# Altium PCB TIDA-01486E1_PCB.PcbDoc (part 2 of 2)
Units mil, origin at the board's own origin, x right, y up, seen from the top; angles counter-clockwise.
Board outline 4100 x 3000 mil, 4 copper layers (Top Layer, Signal Layer 1, Signal Layer 2, Bottom Layer), stack 61.6 mil thick; 140 components, 71 nets, 368 pads, 137 vias.
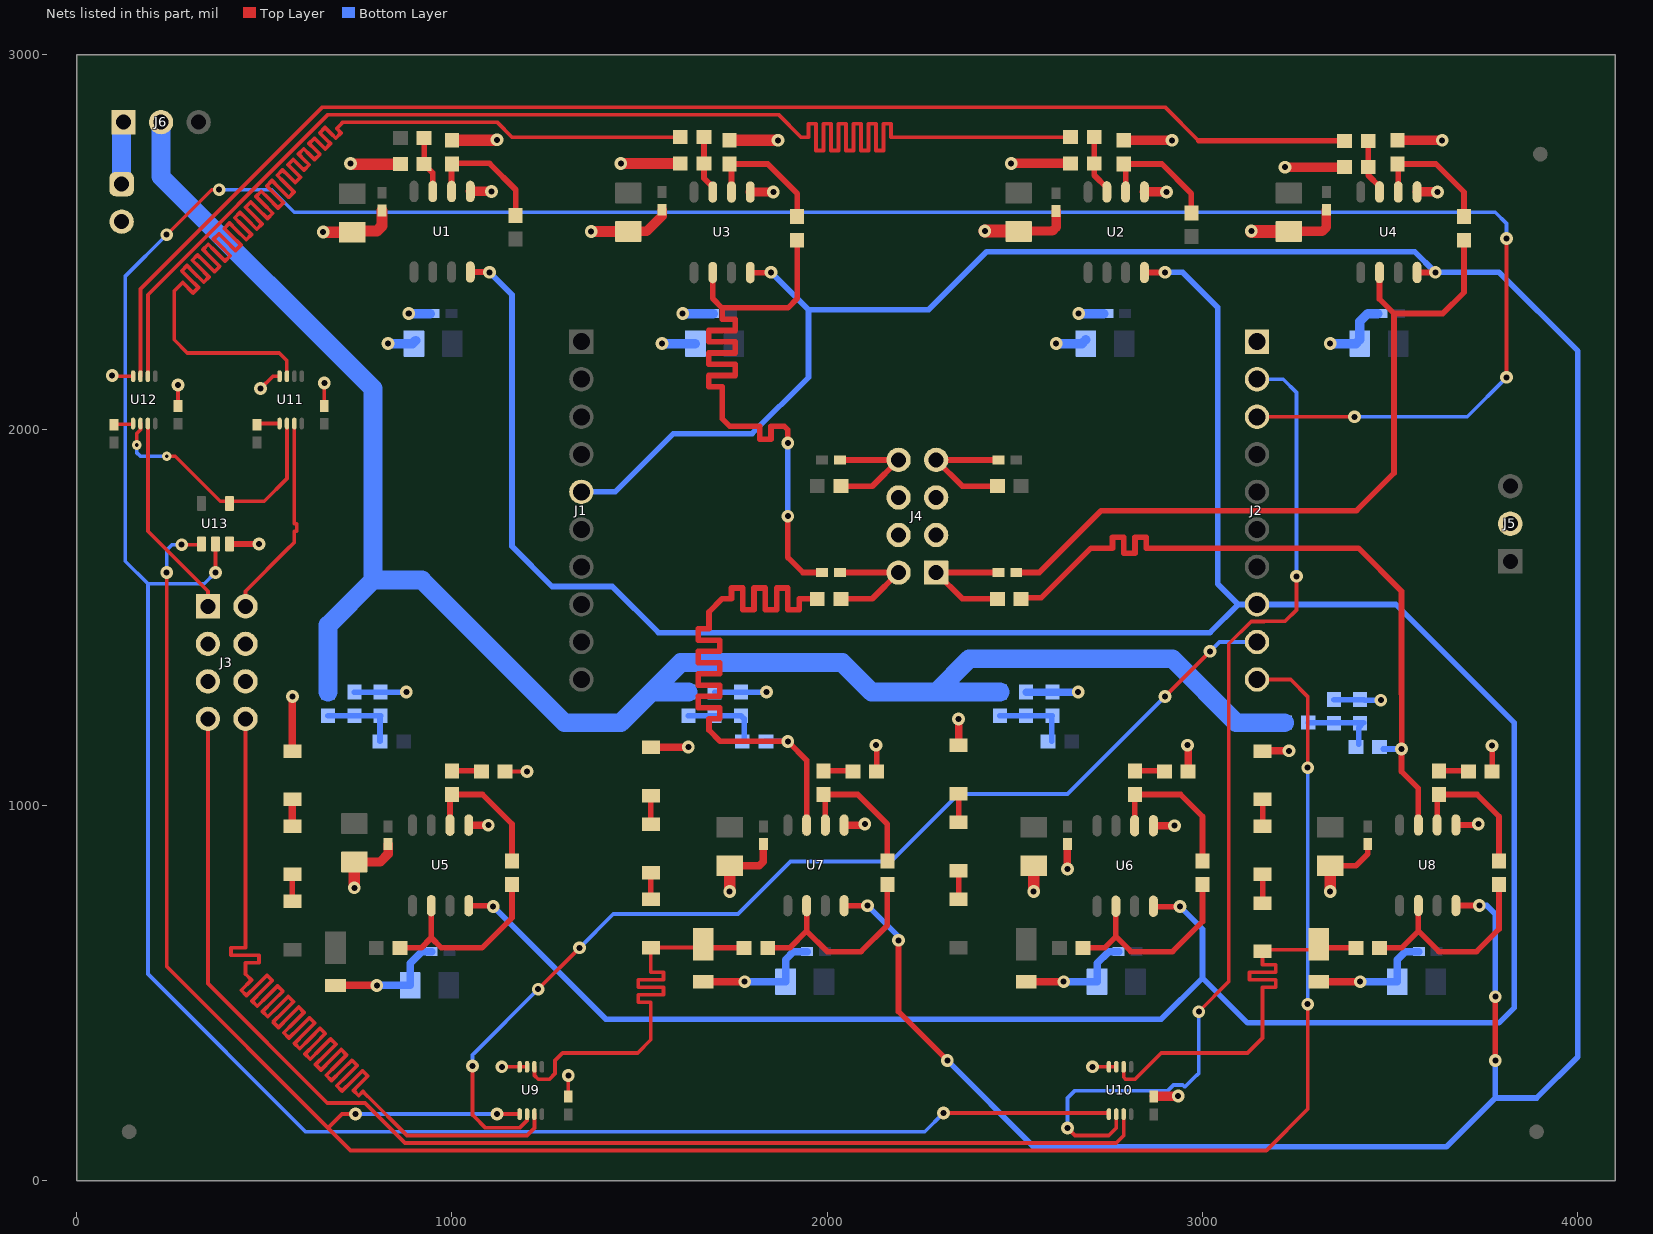
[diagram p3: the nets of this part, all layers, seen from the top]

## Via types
v1: diameter 34, hole 16, Top Layer to Bottom Layer, 129 vias
v2: diameter 40, hole 20, Top Layer to Bottom Layer, 6 vias
v3: diameter 26, hole 10, Top Layer to Bottom Layer, 2 vias

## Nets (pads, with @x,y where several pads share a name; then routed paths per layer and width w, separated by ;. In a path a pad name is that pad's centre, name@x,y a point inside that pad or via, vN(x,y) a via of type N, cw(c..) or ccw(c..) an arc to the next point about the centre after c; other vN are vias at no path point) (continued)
CH1_T: C2.2 U12.2 | length 3678.2
  Top Layer w10: U12.2@190.16,2143.31 190.16,2360.16 670,2840 1870,2840 1930,2780 1940,2780 1950,2780 1950,2815.43 1970,2815.43 1970,2780 1970,2744.57 1990,2744.57 1990,2780 1990,2815.43 2010,2815.43 2010,2780 2010,2744.57 2030,2744.57 2030,2780 2030,2815.43 2050,2815.43 2050,2780 2050,2744.57 2070,2744.57 2070,2780 2070,2815.43 2090,2815.43 2090,2780 2090,2744.57 2110,2744.57 2110,2780 2110,2815.43 2130,2815.43 2130,2780 2130,2744.57 2150,2744.57 2150,2780 2150,2815.43 2170,2815.43 2170,2780 2340,2780 C2.2@2648.5,2780
CH2_IN: C25.1 R31.2 U7.3 | length 1955.1
  Top Layer w15: U7.3@1945,946.97 1945,1120 v1(1895,1170) 1715,1170 1685,1200 1685,1230 1713.96,1230 1713.96,1260 1685,1260 1656.04,1260 1656.04,1290 1685,1290 1713.96,1290 1713.96,1320 1685,1320 1656.04,1320 1656.04,1350 1685,1350 1713.96,1350 1713.96,1380 1685,1380 1656.04,1380 1656.04,1410 1685,1410 1713.96,1410 1713.96,1440 1685,1440 1656.04,1440 1656.04,1470 1685,1470 1685,1500 1685,1515 1720,1550 1745,1550 1745,1578.96 1775,1578.96 1775,1550 1775,1521.04 1805,1521.04 1805,1550 1805,1578.96 1835,1578.96 1835,1550 1835,1521.04 1865,1521.04 1865,1550 1865,1578.96 1895,1578.96 1895,1550 1895,1521.04 1925,1521.04 1925,1550 1940,1550 C25.1@1973.5,1550
  Bottom Layer w15: R31.2@1834.45,1170 1841.5,1170 v1@1894.45,1170
CH2_OUT: R7.2 R37.2 U3.6 | length 1894.9
  Top Layer w15: U3.6@1695,2419.2 1695,2350 1720,2325 ; v1(1895,1770) 1895,1660 1935,1620 R37.2@1986.38,1620 ; v1(1895,1965) 1895,2000 1885,2010 1860,2010 1850,2010 1850,1974.67 1820,1974.67 1820,2010 1790,2010 1775,2010 1740,2010 1720,2030 1720,2115 1684.67,2115 1684.67,2145 1720,2145 1755.33,2145 1755.33,2175 1720,2175 1684.67,2175 1684.67,2205 1720,2205 1755.33,2205 1755.33,2235 1720,2235 1684.67,2235 1684.67,2265 1720,2265 1755.33,2265 1755.33,2295 1720,2295 1720,2310 1720,2325 ; R7.2@1920,2505 1920,2350 1895,2325 1720,2325
  Bottom Layer w15: v1(1895,1770) v1(1895,1965)
CH2_R: D3.1 D11.2 R41.2 U9.2 | length 1162.8
  Top Layer w10: U9.2@1219.84,302.99 1219.84,280.16 1230,270 1260,270 1275,285 1275,320 1295,340 1495,340 1530,375 1530,425 1530,475 1496.25,475 1496.25,495 1530,495 1563.75,495 1563.75,515 1530,515 1496.25,515 1496.25,535 1530,535 1563.75,535 1563.75,555 1530,555 1530,565 1530,621.26 D3.1@1666.26,621.26
  Top Layer w15: D3.1@1680.2,620 R41.2@1778.5,620
  Top Layer w20: D3.1@1672.6,627.6 D3.1@1680.2,620
CH2_T: C3.2 U11.3 | length 3678.5
  Top Layer w10: U11.3@560,2143 560,2185 540,2205 295,2205 260,2240 260,2370 282.81,2392.81 310.55,2365.06 324.69,2379.2 296.95,2406.95 280.13,2423.77 294.27,2437.92 311.09,2421.09 338.84,2393.35 352.98,2407.49 325.23,2435.23 308.41,2452.06 322.55,2466.2 339.38,2449.38 367.12,2421.63 381.26,2435.77 353.52,2463.52 336.69,2480.34 350.84,2494.48 367.66,2477.66 395.41,2449.91 409.55,2464.06 381.8,2491.8 364.98,2508.63 379.12,2522.77 395.94,2505.94 423.69,2478.2 437.83,2492.34 410.09,2520.09 393.26,2536.91 407.4,2551.05 424.23,2534.23 451.97,2506.48 466.12,2520.62 438.37,2548.37 421.55,2565.19 435.69,2579.34 452.51,2562.51 480.26,2534.77 494.4,2548.91 466.65,2576.65 449.83,2593.48 463.97,2607.62 480.8,2590.8 508.54,2563.05 522.68,2577.19 494.94,2604.94 478.12,2621.76 492.26,2635.9 509.08,2619.08 536.83,2591.34 550.97,2605.48 523.22,2633.22 506.4,2650.05 520.54,2664.19 537.37,2647.37 565.11,2619.62 579.25,2633.76 551.51,2661.51 534.68,2678.33 548.83,2692.47 565.65,2675.65 582.45,2658.85 596.59,2672.99 579.79,2689.79 562.97,2706.62 577.11,2720.76 593.93,2703.93 605.76,2692.11 619.9,2706.25 608.08,2718.08 591.25,2734.9 605.39,2749.04 622.22,2732.22 634.04,2720.39 648.18,2734.54 636.36,2746.36 619.54,2763.18 633.68,2777.33 650.5,2760.5 662.33,2748.68 676.47,2762.82 664.64,2774.64 647.82,2791.47 661.96,2805.61 678.79,2788.79 690.61,2776.96 704.75,2791.11 692.93,2802.93 700,2810 710,2820 1120,2820 1160,2780 C3.2@1608.5,2780
CH3_IN: C23.2 R32.2 U8.3 | length 1955.1
  Top Layer w15: C23.2@2516.5,1550 2516.5,1552.37 2570,1552.37 2702.63,1685 2745,1685 2760,1685 2760,1714.5 2790,1714.5 2790,1685 2790,1670.96 2820,1670.96 2820,1685 2820,1714.5 2850,1714.5 2850,1685 2995,1685 3415,1685 3530,1570 3530,1296.66 3530.88,1295.78 3530.88,1150.88 v1(3530,1150) 3530,1090 3575,1045 U8.3@3575,947.28
  Bottom Layer w15: R32.2@3481.5,1150 v1(3530,1150)
CH3_OUT: R8.2 R35.1 U4.6 | length 2015.3
  Top Layer w15: R35.1@2503.62,1620 2565,1620 2730,1785 3410,1785 3510,1885 3510,2310 ; U4.6@3471.5,2419.52 3471.5,2348.5 3510,2310 ; R8.2@3696.5,2505.31 3696.5,2366.5 3640,2310 3510,2310
CH3_R: D4.1 D14.2 R42.2 U10.2 | length 1140.6
  Top Layer w10: U10.2@2789.84,302.99 2789.84,275.16 2795,270 2820,270 2890,340 3120,340 3160,380 3160,405 3160,515 3194.89,515 3194.89,535 3160,535 3125.11,535 3125.11,555 3160,555 3194.89,555 3194.89,575 3160,575 3160,585 3160,615 D4.1@3315.2,615
  Top Layer w15: D4.1@3315.2,615 3320.2,620 R42.2@3408.5,620
CH3_T: C4.2 U12.3 | length 3678.2
  Top Layer w10: U12.3@170.47,2143.31 170.47,2375.47 655,2860 2900,2860 2990,2770
  Top Layer w15: 2990,2770 C4.2@3378.5,2770
EVM_CH0_IN: J3.8 U9.7 | length 3386.3
  Top Layer w10: J3.8@450,1230 450,1020 450,620 411.68,620 411.68,600 450,600 486.07,600 486.07,580 450,580 450,560 450,550 451.8,548.2 465.94,534.06 438.85,506.96 452.99,492.82 480.09,519.91 507.18,547.01 521.32,532.87 494.23,505.77 467.13,478.68 481.28,464.54 508.37,491.63 535.46,518.72 549.61,504.58 522.51,477.49 495.42,450.39 509.56,436.25 536.65,463.35 563.75,490.44 577.89,476.3 550.8,449.2 523.7,422.11 537.84,407.97 564.94,435.06 592.03,462.16 606.18,448.01 579.08,420.92 551.99,393.82 566.13,379.68 593.22,406.78 620.32,433.87 634.46,419.73 607.37,392.63 580.27,365.54 594.41,351.4 621.51,378.49 648.6,405.59 662.74,391.44 635.65,364.35 608.56,337.26 622.7,323.11 649.79,350.21 676.89,377.3 691.03,363.16 663.93,336.07 636.84,308.97 650.98,294.83 678.08,321.92 705.17,349.02 719.31,334.88 692.22,307.78 665.12,280.69 679.27,266.55 706.36,293.64 733.45,320.73 747.6,306.59 720.5,279.5 693.41,252.4 707.55,238.26 734.64,265.36 761.74,292.45 775.88,278.31 748.79,251.21 737.66,240.09 751.8,225.94 762.93,237.07 770,230 775.24,224.76 775.52,224.76 880.28,120 1200,120 1219.84,139.84 U9.7@1219.84,177.01
EVM_CH0_OUT: J3.2 U11.7 | length 553.2
  Top Layer w10: J3.2@450,1530 450,1570 565,1685 572.07,1692.07 580.16,1700.16 580.16,1710.16 580.16,1730.16 586.31,1730.16 586.31,1750.16 580.16,1750.16 580.16,1815 U11.7@580.16,2017.01
EVM_CH1_IN: J3.7 U10.7 | length 3386.3
  Top Layer w10: J3.7@350,1230 350,525 668.12,206.88 768.12,206.88 875,100 2770,100 2789.84,119.84 U10.7@2789.84,177.01
EVM_CH1_OUT: J3.1 U12.7 | length 553.2
  Top Layer w10: U12.7@190.16,2017.01 190.16,1729.84 350,1570 J3.1@350,1530
EXT_VBIAS: J6.1 J7.1 | length 167.1
  Bottom Layer w50: J7.1@120,2655 120,2815 J6.1@125,2820
GND: C9.2 C10.2 C11.2 C12.2 C13.2 C14.2 C15.2 C16.2 C17.2 C18.2 C19.2 C20.2 C27.1 C28.1 C29.1 C30.1 C31.2 C32.2 C33.2 C34.2 C35.2 C36.2 C37.2 C38.2 C39.2 C40.1 C41.2 C42.1 C43.2 C44.1 C45.2 C46.1 C47.2 C48.2 C49.2 C50.2 C51.2 C52.2 C53.2 C54.2 C55.2 C56.2 C57.2 C58.2 D1.2 D2.2 D3.2 D4.2 D7.1 D10.1 D13.1 D16.1 J2.1 J3.3 J3.4 J3.5 J3.6 J4.3 J4.4 J4.5 J4.6 J5.2 J7.2 R1.1 R2.1 R3.1 R4.1 R9.1 R10.1 R11.1 R12.1 R25.1 R26.1 R27.1 R28.1 U1.1 U2.1 U3.1 U4.1 U5.1 U6.1 U7.1 U8.1 U9.3 U9.4 U10.3 U10.4 U11.4 U12.4 U13.3 | length 6917.7
  Top Layer w10: v1@85,2142.99 U12.4@150.47,2142.99 ; C56.2@270,2063.62 v1(270,2120) ; v1(490,2110) 522.99,2142.99 U11.4@540.79,2142.99 ; C55.2@660,2063.62 v1(660,2125) ; v1(1132.99,302.99) U9.4@1180.47,302.99 U9.3@1200.16,302.99 ; C47.2@1141.5,1090 v1(1200,1090) ; C57.2@1310,223.62 v1(1310,280) ; v1(2707.01,302.99) U10.4@2750.47,302.99 U10.3@2770.16,302.99
  Top Layer w15: U13.3@407.4,1695.87 v1(485.87,1695.87) ; v1(2130,1160) 2131.5,1158.5 C49.2@2131.5,1090 ; C58.2@2870,223.62 C58.2@2871.38,225 ; C46.1@3340,838.82 3408.82,838.82 3440,870 C45.2@3440,896.38 ; U8.1@3675,947.28 v1@3737.28,947.28 ; C50.2@3771.5,1090 v1(3771.5,1158.5)
  Top Layer w20: D7.1@575,1150 v1(575,1290) ; D1.2@690,519.8 v1(800,519.8) ; U5.1@1045,946.97 v1(1096.97,946.97) ; D13.1@1530,1154.47 1629.47,1154.47 v1(1630,1155) ; D3.2@1670,529.8 v1@1779.8,529.8 ; C44.1@1740,838.82 1818.82,838.82 1830,850 C43.2@1830,896.38 ; U7.1@2045,946.97 v1@2096.97,946.97 ; D10.1@2350,1158.74 v1(2350,1230) ; D2.2@2530,529.8 v1@2629.8,529.8 ; v1(2640,830) C41.2@2640,896.38 ; U6.1@2869.04,945.43 v1(2925.43,945.43) ; C48.2@2961.5,1090 v1@2961.5,1158.5 ; D16.1@3170.53,1145 v1@3225,1145 ; D4.2@3310,529.8 3310.2,530 v1(3420,530)
  Top Layer w25: C40.1@740,848.82 808.82,848.82 830,870 C39.2@830,896.38 ; U1.1@1049.04,2635.43 v1(1105.43,2635.43) ; C29.1@1470,2528.82 1518.82,2528.82 1560,2570 C14.2@1560,2586.38 ; U3.1@1795,2633.77 v1(1856.23,2633.77) ; v1(2490,2710) R2.1@2648.5,2710 ; C28.1@2508.82,2530 2600,2530 2610,2540 C12.2@2610,2583.18 ; R10.1@2800,2771.5 v1(2918.5,2771.5) ; U2.1@2845,2634.09 v1(2904.09,2634.09) ; C58.2@2871.38,225 v1(2935,225) ; v1(3220,2700) R4.1@3378.5,2700 ; C30.1@3230,2528.82 3318.82,2528.82 3330,2540 C16.2@3330,2586.38 ; R12.1@3520,2771.5 v1(3638.5,2771.5) ; U4.1@3571.5,2634.09 v1(3625.91,2634.09)
  Top Layer w30: v1(656.97,2526.97) C27.1@734.36,2526.97 737.39,2530 800,2530 814.04,2544.04 C10.2@814.04,2584.84 ; v1(730,2710) 731.85,2708.15 R1.1@862.86,2708.15 ; v1(740,780) C40.1@740,848.82 ; R9.1@1000,2771.5 1118.5,2771.5 v1(1120,2772.99) ; v1(1371.18,2528.82) C29.1@1470,2528.82 ; v1(1450,2710) R3.1@1608.5,2710 ; v1(1740,770) C44.1@1740,838.82 ; R11.1@1740,2771.5 v1(1868.5,2771.5) ; v1(2550,770) C42.1@2550,838.82 ; v1(3340,770) C46.1@3340,838.82
  Top Layer w35: v1(2420,2530) C28.1@2508.82,2530 ; v1@3131.18,2528.82 C30.1@3230,2528.82
  Bottom Layer w15: R25.1@740,1301.5 C51.2@810,1301.5 v1(878.5,1301.5) ; R27.1@1700,1301.5 v1(1838.5,1301.5) ; R28.1@3350.07,1281.5 3430.26,1281.5 3431.75,1280 v1(3475,1280)
  Bottom Layer w20: v1(800,519.8) 888.62,519.8 C35.2@888.82,520 888.82,578.82 920,610 C17.2@946.38,610 ; v1(1780,530) C37.2@1888.82,530 1888.82,588.82 1910,610 C19.2@1946.38,610 ; R26.1@2530,1301.5 v1(2668.5,1301.5) ; v1(2630,530) C36.2@2718.82,530 2718.82,578.82 2750,610 C18.2@2776.38,610 ; v1(3420,530) C38.2@3518.82,530 3518.82,588.82 3540,610 C20.2@3576.38,610
  Bottom Layer w25: v1(830,2230) 895.03,2230 C31.2@903.18,2238.15 ; v1(885,2310) C9.2@942.59,2310 ; v1(1560,2230) C33.2@1648.82,2230 ; v1(1615,2310) C13.2@1696.38,2310 ; v1(2610,2230) 2678.82,2230 C32.2@2688.82,2240 ; v1(2670,2310) C11.2@2736.38,2310 ; v1(3340,2230) 3408.82,2230 3418.82,2240 3418.82,2288.82 3440,2310 C15.2@3466.38,2310
  other v1: 2100,950 3734.57,950 3230,1145 2960,1160 95,2145 3130,2530
NetC1_1: C1.1 R1.2 U1.3 | length 152.3
  Top Layer w15: C1.1@925.85,2778.15 R1.2@925.85,2708.15 949.04,2684.96 U1.3@949.04,2635.43
NetC2_1: C2.1 R2.2 U2.3 | length 159.8
  Top Layer w15: C2.1@2711.5,2780 R2.2@2711.5,2710 2711.5,2678.5 2745,2645 U2.3@2745,2634.09
NetC3_1: C3.1 R3.2 U3.3 | length 156
  Top Layer w15: C3.1@1671.5,2780 R3.2@1671.5,2710 1671.5,2670.66 1695,2647.16 U3.3@1695,2633.77
NetC4_1: C4.1 R4.2 U4.3 | length 148.3
  Top Layer w15: C4.1@3441.5,2770 R4.2@3441.5,2700 3441.5,2678.5 3471.5,2648.5 U4.3@3471.5,2634.09
NetC23_1: C23.1 J4.1 R35.2 | length 360.4
  Top Layer w15: C23.1@2455,1550 C23.1@2453.5,1550 2360,1550 J4.1@2290,1620 R35.2@2456.38,1620
NetC24_1: C24.1 J4.7 R36.2 | length 360.4
  Top Layer w15: C24.1@2455,1850 C24.1@2453.5,1850 2360,1850 J4.7@2290,1920 R36.2@2456.38,1920
NetC25_2: C25.2 J4.2 R37.1 | length 334
  Top Layer w15: R37.1@2035,1620 J4.2@2190,1620 2120,1550 C25.2@2040,1550
NetC26_2: C26.2 J4.8 R38.1 | length 334
  Top Layer w15: R38.1@2035,1920 J4.8@2190,1920 2120,1850 C26.2@2040,1850
NetC47_1: C47.1 R17.1 | length 79.1
  Top Layer w15: R17.1@1000,1091.5 1077.01,1091.5 C47.1@1078.5,1090
NetC48_1: C48.1 R18.1 | length 79.1
  Top Layer w15: R18.1@2820,1091.5 2897.01,1091.5 C48.1@2898.5,1090
NetC49_1: C49.1 R19.1 | length 77
  Top Layer w15: R19.1@1990,1091.5 C49.1@2067.01,1091.5
NetC50_1: C50.1 R20.1 | length 79.1
  Top Layer w15: R20.1@3630,1091.5 3707.01,1091.5 C50.1@3708.5,1090
NetC51_1: C51.1 R21.2 R25.2 R29.1 | length 207
  Bottom Layer w15: R21.2@670,1238.5 760,1238.5 C51.1@810,1238.5 ; R29.1@808.5,1170 C51.1@808.5,1237.01
NetC52_1: C52.1 R22.2 R26.2 R30.1 | length 207
  Bottom Layer w15: R22.2@2460,1238.5 R26.2@2530,1238.5 C52.1@2600,1238.5 ; R30.1@2598.5,1170 C52.1@2598.5,1237.01
NetC53_1: C53.1 R23.2 R27.2 R31.1 | length 212
  Bottom Layer w15: R23.2@1630,1238.5 C53.1@1770,1238.5 1778.5,1230 R31.1@1778.5,1170
NetC54_1: C54.1 R24.2 R28.2 R32.1 | length 210
  Bottom Layer w15: R24.2@3281.5,1220 3428.76,1220 3416,1207.24 R32.1@3416,1162.5
NetD5_1: D5.1 D6.2 | length 75
  Top Layer w15: D5.1@575,740 D6.2@575,815
NetD6_1: D6.1 D7.2 | length 70.5
  Top Layer w20: D6.1@575,944.47 D7.2@575,1015
NetD8_1: D8.1 D9.2 | length 70.5
  Top Layer w15: D8.1@2350,749.47 D9.2@2350,820
NetD9_1: D9.1 D10.2 | length 77.6
  Top Layer w15: D10.2@2345,1030 2350,1025 D9.1@2350,954.47
NetD11_1: D11.1 D12.2 | length 60.5
  Top Layer w15: D11.1@1530,749.47 D12.2@1530,810
NetD12_1: D12.1 D13.2 | length 75.5
  Top Layer w15: D12.1@1530,949.47 D13.2@1530,1025
NetD14_1: D14.1 D15.2 | length 60
  Top Layer w15: D14.1@3160,745 D15.2@3160,805
NetD15_1: D15.1 D16.2 | length 77.6
  Top Layer w15: D16.2@3155,1010 3160,1005 D15.1@3160,934.47
NetR5_1: R5.1 R9.2 U1.2 | length 330.8
  Top Layer w15: U1.2@999.04,2635.43 R9.2@999.04,2709.04 ; R9.2@1006.25,2714.76 1011.01,2710 1100,2710 1170,2640 1170,2585.92 R5.1@1164.04,2579.96
NetR6_1: R6.1 R10.2 U2.2 | length 323.6
  Top Layer w15: U2.2@2795,2634.09 R10.2@2795,2703.5 ; R10.2@2800,2708.5 2891.5,2708.5 2970,2630 R6.1@2970,2578.3
NetR7_1: R7.1 R11.2 U3.2 | length 351
  Top Layer w15: U3.2@1745,2633.77 1745,2703.5 R11.2@1740,2708.5 1841.5,2708.5 1920,2630 R7.1@1920,2568.3
NetR8_1: R8.1 R12.2 U4.2 | length 347.8
  Top Layer w15: U4.2@3521.5,2634.09 3521.5,2707.01 R12.2@3520,2708.5 3621.5,2708.5 3696.5,2633.5 R8.1@3696.5,2568.3
NetR13_1: R13.1 R17.2 U5.2 | length 374.6
  Top Layer w15: U5.2@995,946.97 995,1023.5 R17.2@1000,1028.5 1081.5,1028.5 1160,950 R13.1@1160,851.5
NetR13_2: R13.2 R39.1 U5.6 | length 527.9
  Top Layer w15: R39.1@861.5,620 918.19,620 945,646.81 ; U5.6@945,732.4 945,646.81 ; R13.2@1160,788.5 1160,700 1080,620 971.81,620 945,646.81
NetR14_1: R14.1 R18.2 U6.2 | length 406.2
  Top Layer w15: U6.2@2819.04,945.43 2819.04,1027.55 R18.2@2820,1028.5 2941.5,1028.5 3000,970 R14.1@3000,851.5
NetR14_2: R14.2 R40.1 U6.6 | length 560
  Top Layer w15: R40.1@2681.5,620 2739.13,620 2769.04,649.91 ; U6.6@2769.04,730.87 2769.04,649.91 ; R14.2@3000,788.5 3000,690 2920,610 2808.95,610 2769.04,649.91
NetR15_1: R15.1 R19.2 U7.2 | length 384.6
  Top Layer w15: R19.2@1990,1028.5 2081.41,1028.5 2160,949.91 R15.1@2160,851.5 ; U7.2@1995,946.97 R19.2@1995,1023.5
  Top Layer w20: R19.2@1990,1028.5 R19.2@1995,1023.5
NetR15_2: R15.2 R41.1 U7.6 | length 564.8
  Top Layer w15: R41.1@1841.5,620 1900,620 1945,665 ; U7.6@1945,732.4 1945,665 ; R15.2@2160,788.5 2160,680 2090,610 2000,610 1945,665
NetR16_1: R16.1 R20.2 U8.2 | length 386
  Top Layer w15: U8.2@3625,947.28 3625,1023.5 R20.2@3630,1028.5 3731.5,1028.5 3790,970 R16.1@3790,851.5
NetR16_2: R16.2 R42.1 U8.6 | length 571
  Top Layer w15: R42.1@3471.5,620 3530,620 3575,665 ; U8.6@3575,732.72 3575,665 ; R16.2@3790,788.5 3790,670 3730,610 3630,610 3575,665
NetR43_2: R43.2 U11.5 | length 57.1
  Top Layer w10: R43.2@483.71,2017.01 U11.5@540.79,2017.01
NetR44_2: R44.2 U12.5 | length 50.5
  Top Layer w10: R44.2@100,2014.76 U12.5@150.47,2014.76
NetU11_6: U11.6 U12.6 U13.4 | length 707.2
  Top Layer w10: v3(160,1960) 160,1990 170.47,2000.47 U12.6@170.47,2017.01 ; v3(240,1930) 262.68,1930 382.68,1810 500,1810 560.47,1870.47 U11.6@560.47,2017.01
  Bottom Layer w10: v3(160,1960) 160,1940 170,1930 v3(240,1930)
PD1: J2.8 U1.8 U2.8 U5.8 U6.8 | length 8844.3
  Top Layer w15: U5.8@1045,732.4 v1@1107.6,732.4 ; U1.8@1049.04,2420.87 v1@1099.13,2420.87 ; U2.8@2845,2419.52 v1@2899.52,2419.52 ; U6.8@2869.04,730.87 2869.91,730 v1(2940,730)
  Bottom Layer w15: v1(1100,2420) 1160,2360 1160,1690 1267.15,1582.85 1427.15,1582.85 1550,1460 3020,1460 3095,1535 ; v1(1110,730) 1410,430 2890,430 3000,540 ; v1(2900,2420) 2946.8,2420 3040,2326.8 3040,1590 3095,1535 ; v1(2940,730) 3000,670 3000,540 ; 3000,540 3120,420 3790,420 3830,460 3830,1220 3515,1535 J2.8@3145,1535 3095,1535
PD2: J1.5 U3.8 U4.8 U7.8 U8.8 | length 8301
  Top Layer w15: U3.8@1795,2419.2 v1@1849.2,2419.2 ; U7.8@2045,732.4 v1(2107.6,732.4) ; v1(2190,640) 2190,450 v1(2320,320) ; U4.8@3571.5,2419.52 v1@3619.52,2419.52 ; U8.8@3675,732.72 v1(3737.28,732.72) ; v1(3780,320) v1(3780,490)
  Bottom Layer w15: J1.5@1345,1835 1435,1835 1590,1990 1800,1990 1950,2140 1950,2320 ; v1(1850,2420) 1950,2320 ; v1(2107.6,732.4) 2190,650 v1(2190,640) ; v1(2320,320) 2550,90 3650,90 3780,220 ; v1(3737.28,732.72) 3757.28,732.72 3780,710 v1(3780,490) ; v1(3780,320) 3780,220 ; 1950,2320 2270,2320 2425,2475 3565,2475 v1(3620,2420) 3790,2420 4000,2210 4000,330 3890,220 3780,220
S1: J2.9 U9.6 | length 2890.2
  Top Layer w10: v1(1055,305) 1055,175 1060,170 1089.63,140.37 1180.37,140.37 1200.16,160.16 U9.6@1200.16,177.01 ; v1(1230,510) v1(1340,620) ; v1(2900,1290) v1(3020,1410)
  Bottom Layer w10: v1(1055,305) 1055,335 1060,340 v1(1230,510) ; v1(1340,620) 1430,710 1762,710 1902,850 2170,850 2350,1030 2640,1030 v1(2900,1290) ; v1(3020,1410) 3045,1435 J2.9@3145,1435
S2: J2.10 U9.5 U13.1 | length 6277.1
  Top Layer w10: v1(240,1620) 240,570 670,140 ; v1(280,1694.13) 330.87,1694.13 U13.1@332.6,1695.87 ; v1(742.99,177.01) 707.01,177.01 670,140 ; v1(1120,177.01) U9.5@1180.47,177.01 ; J2.10@3145,1335 3235,1335 3280,1290 v1(3280,1100) ; v1(3280,470) 3280,190 3170,80 730,80 670,140
  Bottom Layer w10: v1(240,1620) 240,1680 254.13,1694.13 v1(280,1694.13) ; v1(742.99,177.01) v1(1120,177.01) ; v1(3280,470) v1(3280,1100)
S3: J2.2 U10.6 | length 2739.2
  Top Layer w10: v1(2640,140) 2660,120 2750,120 2770.16,140.16 U10.6@2770.16,177.01 ; v1(2990,450) 3070,530 3070,1430 3129.65,1489.65 3163.79,1489.65 3164.14,1490 3220,1490 3250,1520 v1(3250,1610)
  Bottom Layer w10: v1(2640,140) 2640,220 2659,239 2906.75,239 2922.63,254.87 2947.37,254.87 2952.62,249.62 2985,282 ; 2986,281 2990,285 v1(2990,450) ; J2.2@3145,2135 3215,2135 3250,2100 v1(3250,1610)
S4: J2.3 U10.5 U13.2 | length 9840.8
  Top Layer w10: v1(240,2520) 360,2640 v1(380,2640) ; v1(370,1620) U13.2@370,1695.87 ; v1(2310,180) 2747.48,180 U10.5@2750.47,177.01 ; J2.3@3145,2035 v1(3405,2035) ; v1(3810,2140) v1(3810,2510)
  Bottom Layer w10: v1(240,2520) 130,2410 129.87,2410 129.87,1650.13 190,1590 ; v1(370,1620) 340,1590 190,1590 ; v1(380,2640) 520,2640 580,2580 3780,2580 3810,2550 v1(3810,2510) ; v1(2310,180) 2260,130 610,130 190,550 190,1590 ; v1(3405,2035) 3705,2035 v1(3810,2140)
VBIAS: J6.2 R21.1 R22.1 R23.1 R24.1 | length 4857.5
  Bottom Layer w50: J6.2@225,2815 225,2675 790,2110 790,1600 ; R21.1@670,1301.5 670,1480 790,1600 ; R23.1@1630,1301.5 1531.5,1301.5 ; R22.1@2460,1301.5 2290,1301.5 ; R24.1@3218.5,1220 3090,1220 2920,1390 2378.5,1390 2290,1301.5 ; 790,1600 920,1600 1300,1220 1450,1220 1531.5,1301.5 ; 1531.5,1301.5 1610,1380 2040,1380 2118.5,1301.5 2290,1301.5
pads on no net: FID1.1 FID2.1 FID3.1 J1.2 J1.3 J1.4 J1.6 J1.7 J1.8 J1.9 J1.10 J2.4 J2.5 J2.6 J2.7 U1.5 U2.5 U3.5 U4.5 U5.5 U6.5 U7.5 U8.5 U11.1 U12.1

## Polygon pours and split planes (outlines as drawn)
GND on Signal Layer 2 "SIGNAL_LAYER_2_GND_P016" (solid, remove dead copper, pour order 16): 0,3000 4100,3000 4100,0 0,0
-15V on Signal Layer 2 "SIGNAL_LAYER_2_-15V_P002" (solid, remove dead copper, pour order 2): 3750,1810 3900,1810 3900,2780 610,2780 610,2590 3750,2590
+15V on Signal Layer 2 "SIGNAL_LAYER_2_+15V_P004" (solid, remove dead copper, pour order 4): 3900,1690 3900,1405 3470,1405 3470,2200 1023.57,2200 1023.57,2480 2360,2480 3660,2480 3660,1690
3.3V on Signal Layer 2 "SIGNAL_LAYER_2_3.3V_P006" (solid, remove dead copper, pour order 6): 1400,2200 390,2200 390,2880 20,2880 20,80 3300,80 3300,230 160,230 160,1765 840,1765 840,2060 160,2060 160,2720 270,2720 270,2130 1400,2130
-15V on Signal Layer 2 "SIGNAL_LAYER_2_-15V_P012" (solid, remove dead copper, pour order 12): 3750,1810 3950,1810 3950,1060 610,1060 610,880 4050,880 4050,1910 3750,1910
+15V on Signal Layer 2 "SIGNAL_LAYER_2_+15V_P014" (solid, remove dead copper, pour order 14): 930,595 4050,595 4050,380 930,380
GND on Signal Layer 1 "SIGNAL_LAYER_1_GND_P008" (solid, remove dead copper, pour order 8): 0,0 4100,0 4100,3000 0,3000

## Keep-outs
Keep-Out Layer:
  text ".Layer_Name" at 577,-858.49 h60

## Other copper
Top Layer:
  text ".Layer_Name" at 577,-858.49 h60
Bottom Layer:
  text ".Layer_Name" at 577,-858.49 h60

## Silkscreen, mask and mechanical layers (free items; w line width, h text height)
Top Overlay:
  text "EXT" at 50,2900 h72.83
  text "Vb" at 190,2900 h72.83
  text "+3.3V" at 285,2900 h72.83
  text "V+" at 175,2635 h72.83
  text "GND" at 175,2555 h72.83
  text "GND" at 2940.96,2220.92 h72.83
  text "+3.3V" at 1110,2220 h72.83
  text "S3" at 3210,2120 h72.83
  text "S4" at 3210,2010 h72.83
  text "CH0" at 2045,1995 h72.83
  text "CH1" at 2315,1995 h72.83
  text "-15V" at 3600,1840 h72.83
  text "PD2" at 1160,1810 h72.83
  text "GND" at 1980,1760 h72.83
  text "GND" at 2360,1760 h72.83
  text "GND" at 3610,1730 h72.83
  text "+15V" at 3590,1620 h72.83
  text "EVM_CONN" at 410,1600 h72.83
  text "CH1OUT" at 20,1510 h72.83
  text "CH0OUT" at 530,1510 h72.83
  text "PD1" at 3210,1510 h72.83
  text "CH2" at 2045,1465 h72.83
  text "CH3" at 2310,1460 h72.83
  text "S1" at 3210,1410 h72.83
  text "GND" at 110,1360 h72.83
  text "GND" at 530,1360 h72.83
  text "S2" at 3210,1320 h72.83
  text "CH0IN" at 520,1215 h72.83
  text "CH1IN" at 100,1210 h72.83
  text ".Layer_Name" at 577,-858.49 h60
Bottom Overlay:
  region: 2060,2135 1760,2135 1760,2035 2060,2035
  text "'.PRJ_Number'.PCB_Rev-" at 2745,2055 h108.27
  text ".Layer_Name" at 577,-858.49 h60
Top Paste:
  text ".Layer_Name" at 577,-858.49 h60
Bottom Paste:
  text ".Layer_Name" at 577,-858.49 h60
Top Solder:
  text ".Layer_Name" at 577,-858.49 h60
  text ".Layer_Name" at 577,-858.49 h60
Bottom Solder:
  text ".Layer_Name" at 577,-858.49 h60
Drill Guide:
  text ".Layer_Name" at 577,-858.49 h60
M1 Board Outline:
  lines w10: 0,0 0,3000 4100,3000 4100,2900 4100,0 0,0
  text ".Layer_Name" at 577,-858.49 h60
M2 Board Dimensions:
  rectangle: 0,-275 125,-150
  rectangle: 125,-400 500,-275
  lines w7: 0,-275 1000,-275 ; 125,-400 125,-150 ; 250,-400 250,-150 ; 500,-400 500,-150 ; 750,-400 750,-150 ; 0,-400 1000,-400 1000,-150 0,-150 0,-400
  text ".Layer_Name" at 577,-858.49 h60
M3 3D STEP Top:
  text ".Layer_Name" at 577,-858.49 h60
M4 3D STEP Bottom:
  text ".Layer_Name" at 577,-858.49 h60
M5 Assembly Top:
  lines w10: -292,-930.17 6308,-930.17 ; -292,-726.83 6310,-726.83 ; -292,-523.5 -292,-1133.5 3713,-1133.5 6310,-1133.5 6310,-523.5 -291.5,-523.5 -291.5,-1133.5 1284,-1133.5 ; 2173,-1133.5 2173,-523.5 ; 3440,-726.83 3440,-523.5 ; 4280,-726.83 4280,-523.5 ; 4902,-1140 4902,-937.17
  text "COMPONENTS MARKED 'DNP' SHOULD NOT BE POPULATED." at 1153.5,-318.5 h60
  text "ASSEMBLY VARIANT:" at 1153,-434 h60
  text ".VariantName" at 2189,-434 h60
  text "PCB VIEWED FROM TOP SIDE" at -228.5,-655.67 h60
  text "BOARD #:" at 2248,-655.67 h60
  text ".PRJ_Number" at 2793.5,-655.67 h60
  text "REV:" at 3638,-655.67 h60
  text ".PCB_Rev" at 3929.5,-655.67 h60
  text "SVN REV:" at 4476,-655.67 h60
  text ".VersionControl_RevNumber" at 4982,-655.67 h60
  text "TID #:" at 2248,-859 h60
  text ".TID" at 2793.5,-859 h60
  text "PLOT NAME =" at -228.5,-1064.34 h60
  text ".plot_File_Name" at 577,-1064.34 h60
  text "GENERATED    :" at 2250,-1064.34 h60
  text ".Print_Date" at 3119.5,-1064.34 h60
  text ".Print_Time" at 3848.5,-1064.34 h60
  text "TEXAS INSTRUMENTS" at 5113,-1064.34 h60
M6 Assembly Bottom:
  lines w10: -292.5,-727.33 6309.5,-727.33 ; -290.5,-930.67 6309.5,-930.67 ; 1115.5,-1140.5 1115.5,-937.67 ; 1737.5,-727.33 1737.5,-524 ; 2577.5,-727.33 2577.5,-524 ; 3844.5,-1134 3844.5,-524 ; 4733.5,-1134 6309,-1134 6309,-524 -292.5,-524 -292.5,-1134 2304.5,-1134 6309.5,-1134 6309.5,-524
  text "COMPONENTS MARKED 'DNP' SHOULD NOT BE POPULATED." at 6102,-318 h60
  text ".VariantName" at 5058,-434 h60
  text "ASSEMBLY VARIANT:" at 6097,-434 h60
  text ".VersionControl_RevNumber" at 1035.5,-656.17 h60
  text "SVN REV:" at 1541.5,-656.17 h60
  text ".PCB_Rev" at 2088,-656.17 h60
  text "REV:" at 2379.5,-656.17 h60
  text ".PRJ_Number" at 3224,-656.17 h60
  text "BOARD #:" at 3769.5,-656.17 h60
  text "PCB VIEWED FROM BOTTOM SIDE" at 6246,-656.17 h60
  text ".TID" at 3224,-859.5 h60
  text "TID #:" at 3769.5,-859.5 h60
  text "TEXAS INSTRUMENTS" at 904.5,-1064.84 h60
  text ".Print_Time" at 2169,-1064.84 h60
  text ".Print_Date" at 2898,-1064.84 h60
  text "GENERATED    :" at 3767.5,-1064.84 h60
  text ".plot_File_Name" at 5440.5,-1064.84 h60
  text "PLOT NAME =" at 6246,-1064.84 h60
M9 Title Sheet:
  lines w10: -491.5,1041.5 -291.5,1041.5 ; -491.5,3416.5 -291.5,3416.5 ; -491.5,5791.5 -291.5,5791.5 ; 2008.5,-1333.5 2008.5,-1133.5 ; 2008.5,7966.5 2008.5,8166.5 ; 4508.5,-1333.5 4508.5,-1133.5 ; 4508.5,7966.5 4508.5,8166.5 ; 6321,-1133.5 6321,-523.5 11303.5,-523.5 ; 7008.5,-1333.5 7008.5,-1133.5 ; 7008.5,7966.5 7008.5,8166.5 ; 9508.5,-1333.5 9508.5,-1133.5 ; 9508.5,7966.5 9508.5,8166.5 ; 11303.5,-1133.5 11303.5,-523.5 ; 11303.5,-823.5 14303.5,-823.5 ; 11303.5,-223.5 14303.5,-223.5 ; 11304.5,370.5 14304.5,370.5 ; 12008.5,-1333.5 12008.5,-1133.5 ; 12008.5,7966.5 12008.5,8166.5 ; 12808.5,-1123.5 12808.5,-523.5 ; 14303.5,-523.5 11303.5,-523.5 ; 14303.5,76.5 11303.5,76.5 ; 14308.5,66.5 14308.5,-1133.5 ; 14308.5,871 11304.5,871 11303.5,871 11303.5,370.5 11303.5,76.5 ; 14308.5,1041.5 14508.5,1041.5 ; 14308.5,3416.5 14508.5,3416.5 ; 14308.5,5791.5 14508.5,5791.5 ; 11303.5,-523.5 11303.5,76.5 ; 14308.5,-1133.5 14308.5,7966.5 -291.5,7966.5 -291.5,-1133.5 14308.5,-1133.5 ; -491.5,-1333.5 -491.5,8166.5 14508.5,8166.5 14508.5,-1333.5 -491.5,-1333.5
  text "1" at 739.84,8036.5 h70
  text "2" at 3235.5,8036.5 h70
  text "3" at 5724.84,8036.5 h70
  text "4" at 8231.51,8036.5 h70
  text "5" at 10730.5,8036.5 h70
  text "6" at 13235.5,8036.5 h70
  text "A" at -416.5,6893.5 h70
  text "A" at 14383.5,6893.5 h70
  text "B" at -416.5,4513.5 h70
  text "B" at 14383.5,4513.5 h70
  text "C" at -416.5,2138.5 h70
  text "C" at 14383.5,2138.5 h70
  text "PROJECT TITLE:" at 11343.5,277.5 h45
  text ".PRJ_Title" at 11393.5,144.17 h70
  text "DESIGNED FOR:" at 11343.5,-23.5 h45
  text ".PRJ_Customer" at 11393.5,-163.5 h70
  text "D" at -416.5,-231.5 h70
  text "D" at 14383.5,-231.5 h70
  text "FILE NAME:" at 11343.5,-323.5 h45
  text ".PCB_File_Name_No_Path" at 11393.5,-443.5 h70
  text "Texas Instruments (TI) and/or its licensors do not warrant the accuracy or completeness of this specification" at 6374,-605.34 h45
  text "ENGINEER:" at 11343.5,-613.5 h45
  text "LAYOUT BY:" at 12848.5,-613.5 h45
  text "or any information contained therein. TI and/or its licensors do not warrant that this design will meet" at 6329.01,-718 h45
  text ".PRJ_Engineer" at 11393.5,-768.49 h70
  text ".PCB_Layout" at 12899,-768.49 h70
  text "the specifications, will be suitable for your application or fit for any particular purpose, or will operate in" at 6329.01,-830.67 h45
  text ".Layer_Name" at 577,-858.49 h60
  text "ALTIUM DESIGNER VERSION:" at 12848.5,-923.5 h45
  text "an implementation. TI and/or its licensors do not warrant that the design is production worthy. You should" at 6329.01,-943.33 h45
  text "completely validate and test your design implementation to confirm the system functionality for your application." at 6374,-1056 h45
  text ".print_Scale" at 11393.5,-1056.83 h70
  text ".Application_BuildNumber" at 12899,-1056.83 h70
  text "1" at 739.84,-1263.5 h70
  text "2" at 3235.5,-1263.5 h70
  text "3" at 5724.84,-1263.5 h70
  text "4" at 8231.51,-1263.5 h70
  text "5" at 10730.5,-1263.5 h70
  text "6" at 13235.5,-1263.5 h70
M10 Fab Notes:
  drawing of 189 lines, arcs and shapes, not listed
  text "DESIGN INFORMATION" at 12382.02,6356.17 h60
  text "MIN. TRACK WIDTH:" at 11737.46,6224.05 h60
  text "8" at 12833.7,6224.05 h60
  text "MIL" at 12988.46,6224.05 h60
  text "MIN. CLEARANCE:" at 11737.46,6099.92 h60
  text "0.2" at 12773.7,6099.93 h60
  text "mm" at 12988.46,6099.92 h60
  text "MIN. VIA PAD SIZE:" at 11737.46,5975.8 h60
  text "24" at 12803.71,5975.8 h60
  text "MIL" at 12988.46,5975.8 h60
  text "0.05mm (2MIL)" at 12432.46,5845.9 h60
  text "MINIMUM ANNULAR RING" at 11408.23,5837.67 h60
  text "EXTERNAL" at 13140.46,5837.67 h60
  text "PER" at 11608.23,5727.55 h60
  text "IPC-D-275 CLASS 2 LEVEL C" at 11828.23,5727.54 h60
  text "MIL, HOLES" at 13316.46,5627.07 h60
  text "+/-" at 12924,5618.48 h60
  text "+/-" at 13778,5618.48 h60
  text "REGISTRATION TOLERANCES:" at 11408.23,5617.42 h60
  text "METAL" at 12608,5617.42 h60
  text "5" at 13184.2,5617.42 h60
  text "3" at 14017.2,5617.42 h60
  text "MIL" at 14133.46,5617.42 h60
  text "HOLE SIZE TOLERANCE (UNLESS OTHERWISE SPECIFIED):" at 11408.23,5519.1 h60
  text "+/-" at 13778,5516.23 h60
  text "3" at 14017.2,5515.17 h60
  text "MIL" at 14133.46,5515.17 h60
  text "MATERIAL:" at 11333.46,5377.52 h60
  text "FR-4 High Tg" at 12319.9,5249 h60
  text "X" at 12175.46,5241.01 h60
  text "FR-408" at 11754.46,5236.49 h60
  text "OTHER" at 13242.46,5236.49 h60
  text "62 MIL (1.6mm) +/-10%" at 12074.56,5093.46 h60
  text "X" at 11954.46,5091.01 h60
  text "THICKNESS:" at 11408.23,5085.24 h60
  text "OTHER" at 13359.46,5085.24 h60
  text "TOLERANCE:" at 11408.23,4946.92 h60
  text "X" at 12256.46,4946.92 h60
  text "ANSI IPC-6012 TYPE 3 CLASS 2" at 12434.48,4946.92 h60
  text "OTHER +/-" at 12434.46,4802.73 h60
  text "BOW & TWIST:" at 11408.23,4657.54 h60
  text "X" at 12256.46,4657.54 h60
  text "ANSI IPC-6012 TYPE 3 CLASS 2" at 12434.48,4657.54 h60
  text "OTHER +/-" at 12434.46,4510.85 h60
  text "DRILLING:" at 11333.46,4380.23 h60
  text "NC_DRILL FILES" at 13094.46,4275.04 h60
  text "REFERENCE:" at 11408.23,4271.1 h60
  text "X" at 12065.46,4271.01 h60
  text "AS SHOWN" at 12243.46,4271.1 h60
  text "X" at 12966.46,4271.1 h60
  text "OTHER" at 13392.46,4128.85 h60
  text "PTH COPPER THICKNESS:" at 11407.91,4125.32 h60
  text "X" at 12547.14,4125.32 h60
  text "20-30 um" at 12675.14,4125.32 h60
  text "BOARD FINISH:" at 11333.46,3977.73 h60
  text "SILKSCREEN:" at 11488.68,3867.6 h60
  text "X" at 12446.46,3867.6 h60
  text "TOP" at 12563.46,3867.6 h60
  text "X" at 12956.46,3867.6 h60
  text "BOTTOM" at 13074.46,3867.6 h60
  text "SILKSCREEN COLOR:" at 11488.68,3712.41 h60
  text "X" at 12445.46,3712.41 h60
  text "WHITE" at 12563.46,3712.41 h60
  text "OTHER" at 13074.46,3712.41 h60
  text "X" at 12576.46,3568.96 h60
  text "GREEN" at 12694.46,3568.96 h60
  text "OTHER" at 13312.46,3568.96 h60
  text "SOLDER RESIST COLOR:" at 11488.68,3562.1 h60
  text "X" at 12576.46,3414.71 h60
  text "MATTE" at 12694.46,3414.71 h60
  text "SEMI-GLOSS" at 13312,3414.07 h60
  text "IMMERSION GOLD (ENIG)" at 12394.46,3241.94 h60
  text "ENEPIG" at 13732,3234.72 h60
  text "SURFACE FINISH:" at 11333.46,3233.72 h60
  text "X" at 12216.46,3233.72 h60
  text "IMM. TIN/SILVER OR EQUIV" at 11663,3096.4 h60
  text "OTHER" at 13094.46,3092.47 h60
  text "ARRAY/PANEL:" at 11333.46,2937.09 h60
  text "CUT AND TRIM PER M1 BOARD OUTLINE" at 12394.46,2928.87 h60
  text "N.C. ROUTE" at 12394.46,2792.9 h60
  text "X" at 13082.46,2792.9 h60
  text "V. SCORE" at 13260.46,2792.9 h60
  text "CERTIFICATION:" at 11333.46,2663.77 h60
  text "MATERIALS AND WORKMANSHIP FOR ALL PCBS" at 12058.46,2663.77 h60
  text "TO MEET OR EXCEED THE REQUIREMENTS OF:" at 12058.46,2569.71 h60
  text "X" at 11695.97,2441.08 h60
  text "ANSI IPC-A-600F CLASS ->" at 11823.96,2441.08 h60
  text "X" at 13471.97,2441.08 h60
  text "2" at 13581.96,2441.08 h60
  text "1" at 13266.96,2439.58 h60
  text "3" at 13935.96,2439.58 h60
  text "X" at 12507.97,2293.39 h60
  text "RoHS" at 12635.96,2293.39 h60
  text "OTHER" at 13280.36,2293.39 h60
  text "PER ORDER" at 13677.42,2293.39 h60
  text "ALL BOARDS MUST MEET OR EXCEED UL94-V0 REQUIREMENTS." at 11361,2139.57 h60
  text "PCB MUST BEAR THE UL94V-0 UL REGISTERED MATERIAL ID NUMBER" at 11361,2023.5 h60
  text "ADDITIONAL REQUIREMENTS:" at 11333.46,1854.08 h60
  text "MICROSECTION:" at 11408.23,1746.95 h60
  text "YES" at 12313.96,1746.95 h60
  text "REQUIRED" at 13175.46,1602.62 h60
  text "BARE BOARD ELEC. TEST:" at 11408.23,1599.76 h60
  text "NONE" at 12713.96,1599.76 h60
  text "X" at 13057.46,1599.76 h60
  text "PER ORDER" at 13767.46,1599.76 h60
  text "XX MIL VIAS REQUIRE NON-CONDUCTIVE FILL AND PLANARIZE" at 11576.38,1394.82 h59
  text "XX MIL VIAS REQUIRE CONDUCTIVE FILL AND PLANARIZE" at 11584.38,1290.84 h60
  text "OUTER XX MIL VIAS REQUIRE 50 OHM SINGLE-ENDED IMPEDANCE" at 11583.39,1127.46 h58
  text "LAYER 2 & 3 (INNER LAYERS) XX MIL WIDE, XX MIL SPACE / TRACES REQUIRE 100 OHM DIFFERENTIAL IMPEDANCE" at 11575.39,891.74 h60
  text ".Layer_Name" at 577,-858.49 h60
  text ".Layer_Name" at 570,-970 h60
M11 Gerber Information:
  lines w10: -292,-930.17 6308,-930.17 ; -292,-726.83 6310,-726.83 ; -292,-523.5 -292,-1133.5 3713,-1133.5 6310,-1133.5 6310,-523.5 -291.5,-523.5 -291.5,-1133.5 1284,-1133.5 ; 2173,-1133.5 2173,-523.5 ; 3440,-726.83 3440,-523.5 ; 4280,-726.83 4280,-523.5 ; 4902,-1140 4902,-937.17
  text "ALL ARTWORK VIEWED FROM TOP SIDE" at -228.5,-655.67 h60
  text "BOARD #:" at 2248,-655.67 h60
  text ".PRJ_Number" at 2793.5,-655.67 h60
  text "REV:" at 3638,-655.67 h60
  text ".PCB_Rev" at 3929.5,-655.67 h60
  text "SVN REV:" at 4476,-655.67 h60
  text ".VersionControl_RevNumber" at 4982,-655.67 h60
  text "LAYER NAME =" at -228.5,-858.49 h60
  text "TID #:" at 2248,-859 h60
  text ".TID" at 2793.5,-859 h60
  text "PLOT NAME =" at -228.5,-1064.34 h60
  text ".plot_File_Name" at 577,-1064.34 h60
  text "GENERATED    :" at 2250,-1064.34 h60
  text ".Print_Date" at 3119.5,-1064.34 h60
  text ".Print_Time" at 3848.5,-1064.34 h60
  text "TEXAS INSTRUMENTS" at 5113,-1064.34 h60
M12 Stackup:
  drawing of 295 lines, arcs and shapes, not listed
  text "Layer" at 9807.84,7852.5 h60
  text "Name" at 10217.76,7852.5 h60
  text "Material" at 11157.5,7852.5 h60
  text "Thickness" at 12017.26,7852.5 h60
  text "Constant" at 12667.1,7852.5 h60
  text "Board Layer Stack" at 13236.96,7852.5 h60
  text "Top Overlay" at 10217.76,7732.5 h60
  text "Top Solder" at 10217.76,7612.5 h60
  text "Solder Resist" at 11157.5,7612.5 h60
  text "0.40mil" at 12017.26,7612.5 h60
  text "3.5" at 12667.1,7612.5 h60
  text "1" at 9807.84,7492.5 h60
  text "Top Layer" at 10217.76,7492.5 h60
  text "1.40mil" at 12017.26,7492.5 h60
  text "Dielectric 1" at 10217.76,7372.5 h60
  text "FR-4" at 11157.5,7372.5 h60
  text "8.00mil" at 12017.26,7372.5 h60
  text "4.2" at 12667.1,7372.5 h60
  text "2" at 9807.84,7252.5 h60
  text "Signal Layer 1" at 10217.76,7252.5 h60
  text "1.40mil" at 12017.26,7252.5 h60
  text "Dielectric 2" at 10217.76,7132.5 h60
  text "FR-4" at 11157.5,7132.5 h60
  text "40.00mil" at 12017.26,7132.5 h60
  text "4.2" at 12667.1,7132.5 h60
  text "3" at 9807.84,7012.5 h60
  text "Signal Layer 2" at 10217.76,7012.5 h60
  text "1.40mil" at 12017.26,7012.5 h60
  text "Dielectric 3" at 10217.76,6892.5 h60
  text "FR-4" at 11157.5,6892.5 h60
  text "8.00mil" at 12017.26,6892.5 h60
  text "4.2" at 12667.1,6892.5 h60
  text "4" at 9807.84,6772.5 h60
  text "Bottom Layer" at 10217.76,6772.5 h60
  text "1.40mil" at 12017.26,6772.5 h60
  text "Bottom Solder" at 10217.76,6652.5 h60
  text "Solder Resist" at 11157.5,6652.5 h60
  text "0.40mil" at 12017.26,6652.5 h60
  text "3.5" at 12667.1,6652.5 h60
  text "Bottom Overlay" at 10217.76,6532.5 h60
  text ".Layer_Name" at 577,-858.49 h60
M13 Component Bodies Top:
  text ".Layer_Name" at 577,-858.49 h60
M14 Component Bodies Bottom:
  text ".Layer_Name" at 577,-858.49 h60
M15 Courtyards Top:
  text ".Layer_Name" at 577,-858.49 h60
M16 Courtyards Bottom:
  text ".Layer_Name" at 577,-858.49 h60
Drill Drawing:
  circle w10: c5363.54,3012.66 r27.56
  lines w10: 5335.98,2792.17 5391.1,2792.17 5363.54,2737.05 5335.98,2792.17 ; 5335.98,2861.07 5391.1,2861.07 5391.1,2916.2 5335.98,2916.2 5335.98,2861.07 ; 5335.98,3122.91 5349.76,3122.91 5363.54,3109.13 5377.32,3122.91 5391.1,3122.91 5377.32,3136.69 5391.1,3150.47 5377.32,3150.47 5363.54,3164.25 5349.76,3150.47 5335.98,3150.47 5349.76,3136.69 5335.98,3122.91 ; 5335.98,3233.15 5363.54,3246.94 5391.1,3233.15 5377.32,3260.72 5391.1,3288.28 5363.54,3274.5 5335.98,3288.28 5349.76,3260.72 5335.98,3233.15
  lines w12: 5286,2699.84 8512.8,2699.84 ; 5286,3319.97 8512.8,3319.97 ; 5623.36,2575.81 5623.36,3444 ; 5955.06,2575.81 5955.06,3444 ; 6590.91,2575.81 6590.91,3444 ; 6849.71,2575.81 6849.71,3444 ; 7224.46,2575.81 7224.46,3444 ; 7947,2575.81 7947,3444 ; 5286,2575.81 8512.8,2575.81 8512.8,3444 5286,3444 5286,2575.81
  text "Symbol" at 5360.42,3357.18 h72
  text "Quantity" at 5660.57,3357.18 h72
  text "Finished Hole Size" at 5992.26,3357.18 h72
  text "Plated" at 6628.12,3357.18 h72
  text "Hole Type" at 6886.92,3357.18 h72
  text "Drill Layer Pair" at 7261.67,3357.18 h72
  text "Hole Tolerance" at 7984.21,3357.18 h72
  text "2" at 5660.57,3233.15 h60
  text "10.00mil (0.254mm)" at 5992.26,3233.15 h60
  text "PTH" at 6628.12,3233.15 h60
  text "Round" at 6886.92,3233.15 h60
  text "Top Layer - Bottom Layer" at 7261.67,3233.15 h60
  text "129" at 5660.57,3109.13 h60
  text "16.00mil (0.406mm)" at 5992.26,3109.13 h60
  text "PTH" at 6628.12,3109.13 h60
  text "Round" at 6886.92,3109.13 h60
  text "Top Layer - Bottom Layer" at 7261.67,3109.13 h60
  text "6" at 5660.57,2985.1 h60
  text "20.00mil (0.508mm)" at 5992.26,2985.1 h60
  text "PTH" at 6628.12,2985.1 h60
  text "Round" at 6886.92,2985.1 h60
  text "Top Layer - Bottom Layer" at 7261.67,2985.1 h60
  text "24" at 5660.57,2861.07 h60
  text "40.00mil (1.016mm)" at 5992.26,2861.07 h60
  text "PTH" at 6628.12,2861.07 h60
  text "Round" at 6886.92,2861.07 h60
  text "Top Layer - Bottom Layer" at 7261.67,2861.07 h60
  text "20" at 5660.57,2737.05 h60
  text "45.28mil (1.150mm)" at 5992.26,2737.05 h60
  text "PTH" at 6628.12,2737.05 h60
  text "Round" at 6886.92,2737.05 h60
  text "Top Layer - Bottom Layer" at 7261.67,2737.05 h60
  text "181 Total" at 5660.57,2613.02 h60
  text ".Layer_Name" at 577,-858.49 h60
Mechanical 17:
  text ".Layer_Name" at 577,-858.49 h60
Mechanical 18:
  text ".Layer_Name" at 577,-858.49 h60
Mechanical 19:
  text ".Layer_Name" at 577,-858.49 h60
